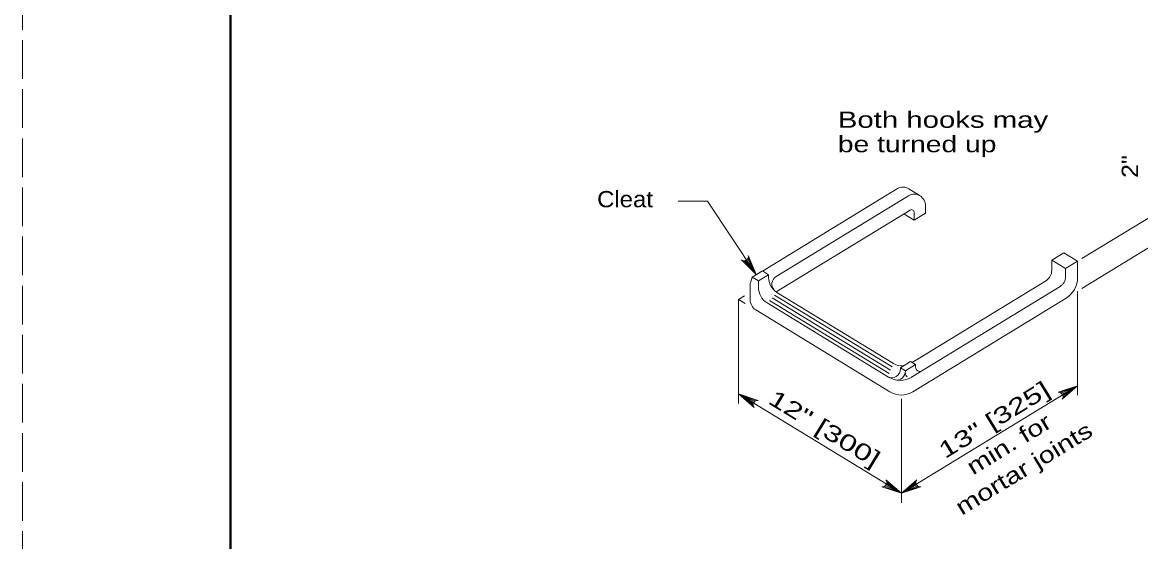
# Model space of a CAD drawing. Extents: x 1083.1 to 1117.1, y 697.4 to 741.4.
# Drawn here: x 1083.13 to 1093.86, y 705.57 to 710.56 of the extents above; entities that cross this region are included whole.
import ezdxf
from ezdxf.enums import TextEntityAlignment as Align

# ---------------------------------------------------------------- set-up
doc = ezdxf.new("R2010")
doc.units = 0
doc.header["$LTSCALE"] = 0.062
doc.linetypes.add('LONG_DASHED', pattern=[7.5, 6, -1.5])
doc.layers.add('1', color=7, linetype='Continuous', lineweight=13)

msp = doc.modelspace()

# ---------------------------------------------------------------- linework, layer by layer
at = {"layer": '1'}
for p, q in [((1090.23292, 708.16675), (1091.52842, 708.95867)), ((1090.36308, 708.11308), (1091.63517, 708.89067)), ((1091.63958, 708.95758), (1091.74633, 708.88958)), ((1091.79942, 708.722), (1091.79942, 708.79033)), ((1090.36283, 707.96692), (1091.64942, 708.75333)), ((1091.68958, 708.65483), (1091.58892, 708.71633)), ((1091.68958, 708.65483), (1091.79942, 708.722)), ((1091.68992, 708.65508), (1091.68992, 708.72858)), ((1093.30033, 708.28675), (1093.98983, 708.70817)), ((1093.01, 708.27092), (1093.12575, 708.34167)), ((1093.25792, 708.26083), (1093.12575, 708.34167)), ((1093.30033, 707.99925), (1093.98983, 708.42067)), ((1090.05467, 708.266), (1090.17292, 708.13467)), ((1090.068, 708.26783), (1090.17292, 708.13467)), ((1090.07933, 708.27325), (1090.17292, 708.13467)), ((1090.09058, 708.28458), (1090.17292, 708.13467)), ((1090.09625, 708.2965), (1090.17292, 708.13467)), ((1093.14225, 708.19017), (1093.01, 708.27092)), ((1093.01, 708.17142), (1093.01, 708.27092)), ((1093.14225, 708.19017), (1093.01, 708.27092)), ((1093.14225, 708.19017), (1093.25792, 708.26083)), ((1093.25792, 708.10567), (1093.25792, 708.26083)), ((1090.13417, 708.10792), (1090.23175, 708.1675)), ((1090.19308, 708.07192), (1090.29067, 708.1315)), ((1090.29067, 708.1315), (1090.23175, 708.1675)), ((1093.14225, 708.11283), (1093.14225, 708.19017)), ((1090.11433, 707.89408), (1090.11433, 708.02675)), ((1090.13417, 708.10792), (1090.12025, 708.0645)), ((1090.19417, 708.07125), (1090.13417, 708.10792)), ((1090.19417, 708.01125), (1090.19417, 708.07125)), ((1091.665, 707.14683), (1093.09067, 708.01833)), ((1091.66917, 707.28883), (1092.9585, 708.07692)), ((1091.46258, 707.21492), (1090.32433, 707.91058)), ((1091.47675, 707.24617), (1090.34825, 707.93592)), ((1091.49092, 707.27742), (1090.37217, 707.96125)), ((1093.25792, 707.97333), (1093.25792, 706.9725)), ((1090.00383, 707.89408), (1090.00383, 706.89325)), ((1091.44367, 707.14667), (1090.27658, 707.86)), ((1091.4485, 707.18358), (1090.3005, 707.88533)), ((1091.67658, 707.00667), (1093.15008, 707.90742)), ((1091.45558, 707.00667), (1090.16958, 707.79275)), ((1091.558, 707.23758), (1091.65558, 707.29717)), ((1091.606, 707.20825), (1091.70358, 707.26783)), ((1091.70358, 707.26783), (1091.65558, 707.29717)), ((1091.70358, 707.24608), (1091.70358, 707.26783)), ((1091.606, 707.20825), (1091.558, 707.23758)), ((1091.558, 707.228), (1091.558, 707.23758)), ((1091.56608, 706.0305), (1093.25792, 707.06467)), ((1093.09108, 706.99958), (1093.25792, 707.06467)), ((1093.10258, 706.99308), (1093.25792, 707.06467)), ((1093.11308, 706.98108), (1093.25792, 707.06467)), ((1093.11767, 706.96942), (1093.25792, 707.06467)), ((1093.11867, 706.956), (1093.25792, 707.06467)), ((1090.14867, 706.90183), (1090.00383, 706.9855)), ((1090.1435, 706.88667), (1090.00383, 706.9855)), ((1090.14367, 706.8735), (1090.00383, 706.9855)), ((1090.15642, 706.91167), (1090.00383, 706.9855)), ((1090.16758, 706.91917), (1090.00383, 706.9855)), ((1090.00383, 706.9855), (1091.56608, 706.0305)), ((1091.56608, 706.93917), (1091.56608, 705.93833)), ((1091.40225, 706.09683), (1091.56608, 706.0305)), ((1091.4135, 706.10433), (1091.56608, 706.0305)), ((1091.42125, 706.11417), (1091.56608, 706.0305)), ((1091.42625, 706.1425), (1091.56608, 706.0305)), ((1091.42642, 706.12933), (1091.56608, 706.0305)), ((1091.70533, 706.13925), (1091.56608, 706.0305)), ((1091.70625, 706.12575), (1091.56608, 706.0305)), ((1091.71092, 706.11417), (1091.56608, 706.0305)), ((1091.72142, 706.10208), (1091.56608, 706.0305)), ((1091.73292, 706.09558), (1091.56608, 706.0305))]:
    msp.add_line(p, q, dxfattribs=at)
at = {"layer": '1', "linetype": 'LONG_DASHED'}
msp.add_lwpolyline([(1083.12642, 697.35408), (1117.12642, 697.35408), (1117.12642, 719.35408), (1083.12642, 719.35408)], close=True, dxfattribs=at)
at = {"layer": '1', "lineweight": 25}
msp.add_lwpolyline([(1116.62642, 697.85408), (1085.12642, 697.85408), (1085.12642, 718.85408)], dxfattribs=at)
at = {"layer": '1', "lineweight": 40}
msp.add_lwpolyline([(1085.12642, 718.85408), (1116.62642, 718.85408), (1116.62642, 697.85408), (1085.12642, 697.85408)], close=True, dxfattribs=at)
at = {"layer": '1'}
for points in [[(1090.17292, 708.13467), (1089.70525, 708.83767), (1089.42175, 708.83767)], [(1090.09675, 708.31642), (1090.17292, 708.13467), (1090.03267, 708.27317)], [(1090.06758, 707.85508), (1090.00383, 707.89408), (1090.0595, 707.92808)], [(1093.07117, 707.0015), (1093.25792, 707.06467), (1093.10983, 706.93458)], [(1090.15192, 706.85533), (1090.00383, 706.9855), (1090.1905, 706.92233)], [(1091.418, 706.16067), (1091.56608, 706.0305), (1091.37933, 706.09367)], [(1091.75275, 706.09367), (1091.56608, 706.0305), (1091.71417, 706.16067)]]:
    msp.add_lwpolyline(points, dxfattribs=at)
for centre, start, end in [((1090.05597, 708.30774), 236.11061, 11.93673), ((1093.07704, 706.9602), 322.08782, 97.91395), ((1090.18475, 706.88105), 82.08782, 217.91395), ((1091.38513, 706.13495), 262.08782, 37.91395), ((1091.74695, 706.13502), 142.08782, 277.91395)]:
    msp.add_arc(centre, 0.04172, start, end, dxfattribs=at)
for centre, major_axis, start_param, end_param in [((1091.58313, 708.85827), (0, 0.11591), 5.74165293, 6.80678573), ((1091.68991, 708.79027), (0, 0.11591), 4.71263522, 6.80678297), ((1091.6629, 708.72854), (0, 0.02859), 4.7123914, 6.80678326), ((1090.45461, 708.11246), (0, -0.17462), 4.61130533, 5.75958745), ((1092.90693, 708.17144), (0, -0.10914), 0.52359858, 1.57079924), ((1090.22483, 708.02675), (0, 0.117), 1.24214031, 1.5709153), ((1090.40297, 708.03993), (0, 0.08447), 0.52359868, 2.31942132), ((1093.03915, 708.11284), (0, 0.10914), 3.66519007, 4.71240905), ((1093.04145, 708.10563), (0, -0.22919), 0.52359829, 1.57079676), ((1090.35907, 708.01124), (0, -0.17462), 4.71238869, 5.75958556), ((1090.22481, 707.89409), (0, -0.117), 4.71238864, 5.75958668), ((1091.57067, 707.42372), (0, -0.16895), 5.75958663, 6.39039807), ((1091.47556, 707.22796), (0, -0.08731), 5.75958546, 7.85398134), ((1091.52354, 707.20625), (0, -0.08731), 6.06044838, 7.85397887), ((1091.64724, 707.18643), (0, 0.04366), 1.57079356, 2.52758539), ((1091.74478, 707.24605), (0, 0.04366), 1.57078983, 3.66519017), ((1091.55414, 707.34931), (0, -0.234), 5.75958367, 6.81860641), ((1091.56606, 707.20935), (0, -0.234), 5.75958653, 6.80678379)]:
    msp.add_ellipse(centre, major_axis=major_axis, ratio=0.944544, start_param=start_param, end_param=end_param, dxfattribs=at)

# ---------------------------------------------------------------- texts
for s, width, p in [('Both hooks may', 1.35, (1090.95642, 709.54342)), ('be turned up', 1.3, (1090.95642, 709.30875)), ('Cleat', 1.1, (1088.64525, 708.77992))]:
    msp.add_text(s, height=0.156, dxfattribs=dict(at, width=width)).set_placement(p)
for s, rotation, width, p in [('2"', 90, 1.15, (1093.83792, 709.17129)), ('13" [325]', 31.435, 1.45, (1092.49703, 706.67124)), ('12" [300]', 328.565, 1.45, (1090.7882, 706.58813)), ('min. for', 31.435, 1.3, (1092.6399, 706.4374)), ('mortar joints', 31.435, 1.3, (1092.78274, 706.20367))]:
    msp.add_text(s, height=0.156, rotation=rotation, dxfattribs=dict(at, width=width)).set_placement(p, align=Align.CENTER)

doc.saveas('drawing.dxf')
